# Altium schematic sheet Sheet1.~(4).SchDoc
size A3
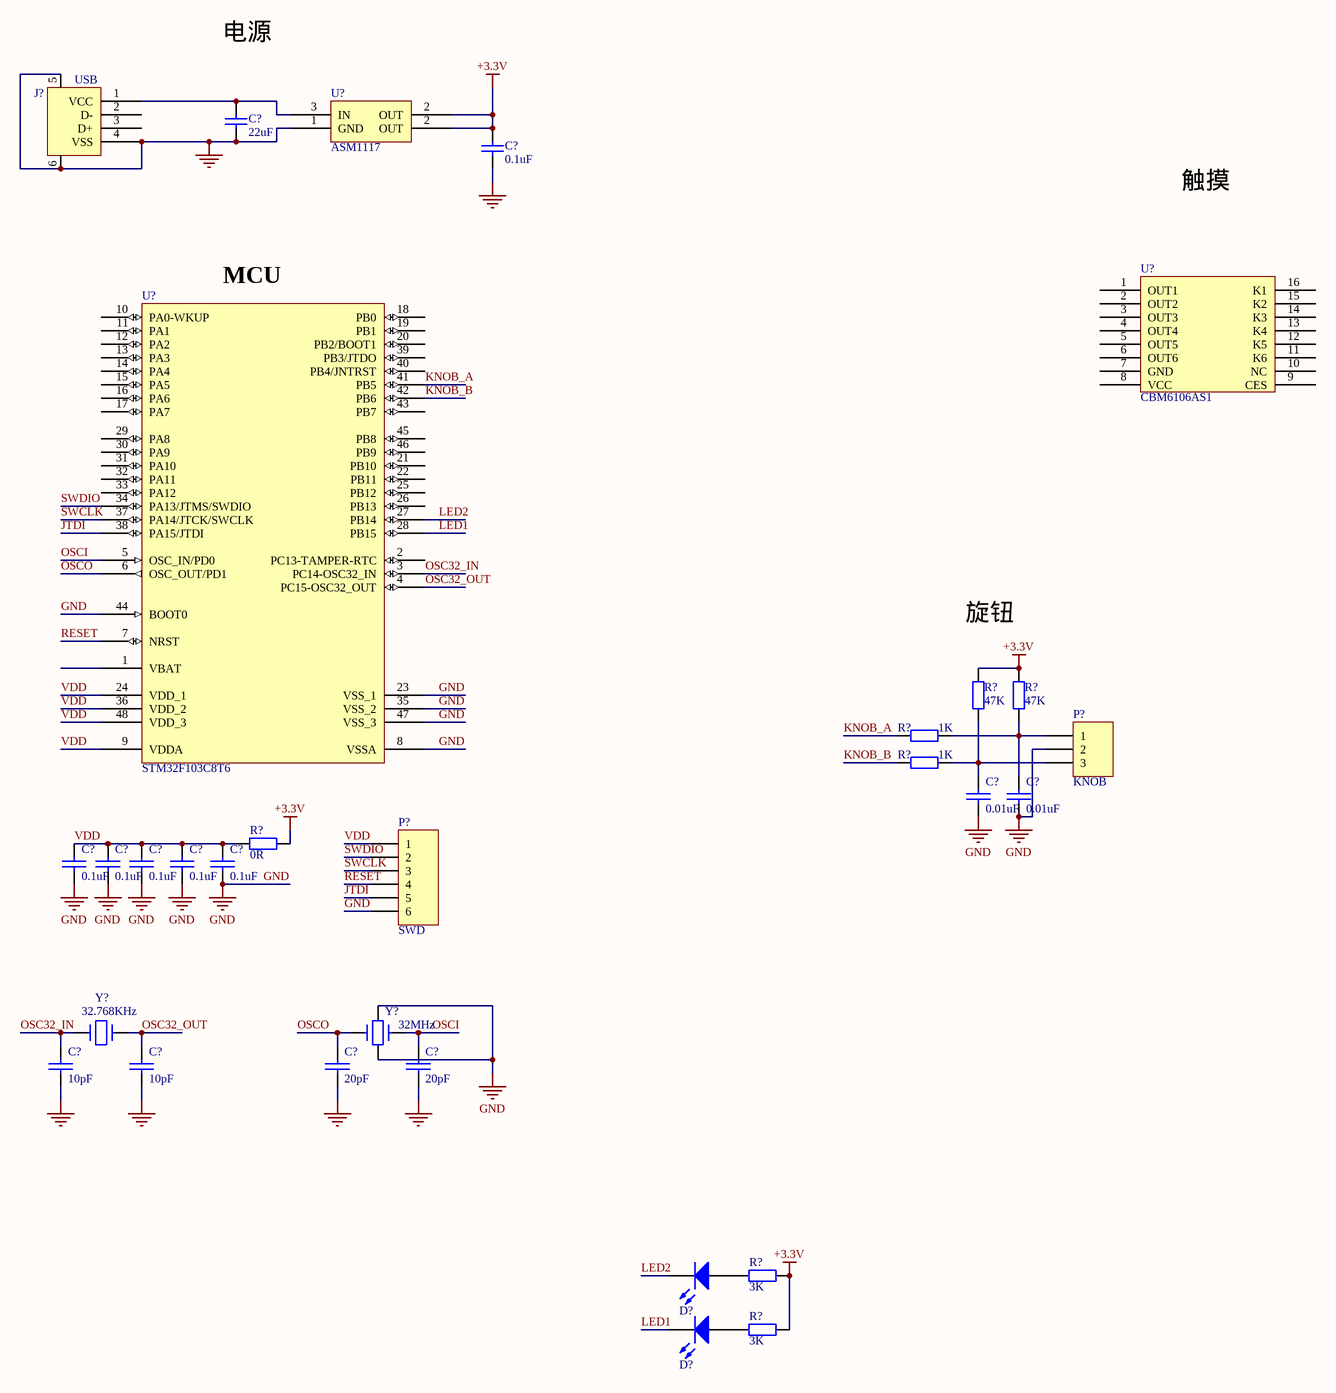
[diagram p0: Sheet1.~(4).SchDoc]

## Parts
(Parts that share a designator on the sheet are numbered #1, #2 ... from top to bottom, then left to right.)
C?#1  value 22uF  [0402C]  (hidden comment: Cap)
C?#2  value 0.1uF  [0402C]  (hidden comment: Cap)
C?#3  0.01uF  [0402C]
C?#4  0.01uF  [0402C]
C?#5  0.1uF  [0402C]
C?#6  0.1uF  [0402C]
C?#7  0.1uF  [0402C]
C?#8  0.1uF  [0402C]
C?#9  0.1uF  [0402C]
C?#10  10pF  [0402C]
C?#11  10pF  [0402C]
C?#12  20pF  [0402C]
C?#13  20pF  [0402C]
D?#1  LED0  [led0603]  (value not drawn)
D?#2  LED0  [led0603]  (value not drawn)
J?  USB  [USB_A1]
P?#1  KNOB  [HDR3X1_A]
P?#2  SWD  [HDR6X1_B2]
R?#1  value 47K  [0603-1]  (hidden comment: Res1)
R?#2  value 47K  [0603-1]  (hidden comment: Res1)
R?#3  value 1K  [0603-1]  (hidden comment: Res1)
R?#4  value 1K  [0603-1]  (hidden comment: Res1)
R?#5  value 0R  [0402R]  (hidden comment: Res1)
R?#6  value 3K  [0402R]  (hidden comment: Res1)
R?#7  value 3K  [0402R]  (hidden comment: Res1)
U?#1  ASM1117  [SOT-223-3]
U?#2  STM32F103C8T6  [LQFP48_N]
U?#3  CBM6106AS1
Y?#1  32.768KHz  [SMD3215]
Y?#2  32MHz  [Y3225]

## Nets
+3.3V: C?#2.2 R?#1.2 R?#2.2 R?#5.2 R?#6.1 R?#7.1 U?#1.2(OUT)
GND: C?#1.1 C?#2.1 C?#3.2 C?#4.2 C?#5.2 C?#6.2 C?#7.2 C?#8.2 C?#9.2 C?#10.2 C?#11.2 C?#12.2 C?#13.2 J?.4(VSS) J?.5 J?.6 P?#1.2 P?#2.6 U?#1.1(GND) U?#2.8(VSSA) U?#2.23(VSS_1) U?#2.35(VSS_2) U?#2.44(BOOT0) U?#2.47(VSS_3) Y?#2.2 Y?#2.4
JTDI: P?#2.5 U?#2.38(PA15/JTDI)
KNOB_A: R?#3.1 U?#2.41(PB5)
KNOB_B: R?#4.1 U?#2.42(PB6)
LED1: D?#2.2(K) U?#2.28(PB15)
LED2: D?#1.2(K) U?#2.27(PB14)
OSC32_IN: C?#10.1 U?#2.3(PC14-OSC32_IN) Y?#1.1
OSC32_OUT: C?#11.1 U?#2.4(PC15-OSC32_OUT) Y?#1.2
OSCI: C?#13.1 U?#2.5(OSC_IN/PD0) Y?#2.3
OSCO: C?#12.1 U?#2.6(OSC_OUT/PD1) Y?#2.1
RESET: P?#2.4 U?#2.7(NRST)
SWCLK: P?#2.3 U?#2.37(PA14/JTCK/SWCLK)
SWDIO: P?#2.2 U?#2.34(PA13/JTMS/SWDIO)
VDD: C?#5.1 C?#6.1 C?#7.1 C?#8.1 C?#9.1 P?#2.1 R?#5.1 U?#2.9(VDDA) U?#2.24(VDD_1) U?#2.36(VDD_2) U?#2.48(VDD_3)
NetC?#1_2: C?#1.2 J?.1(VCC) U?#1.3(IN)
NetC?#3_1: C?#3.1 P?#1.3 R?#1.1 R?#4.2
NetC?#4_1: C?#4.1 P?#1.1 R?#2.1 R?#3.2
NetD?#1_1: D?#1.1(A) R?#6.2
NetD?#2_1: D?#2.1(A) R?#7.2

Not connected (* = marked no-connect by the designer): J? 2(D-) 3(D+); U?#2 1(VBAT) 2(PC13-TAMPER-RTC) 10(PA0-WKUP) 11(PA1) 12(PA2) 13(PA3) 14(PA4) 15(PA5) 16(PA6) 17(PA7) 18(PB0) 19(PB1) 20(PB2/BOOT1) 21(PB10) 22(PB11) 25(PB12) 26(PB13) 29(PA8) 30(PA9) 31(PA10) 32(PA11) 33(PA12) 39(PB3/JTDO) 40(PB4/JNTRST) 43(PB7) 45(PB8) 46(PB9); U?#3 1(OUT1) 2(OUT2) 3(OUT3) 4(OUT4) 5(OUT5) 6(OUT6) 7(GND) 8(VCC) 9(CES) 10(NC) 11(K6) 12(K5) 13(K4) 14(K3) 15(K2) 16(K1)

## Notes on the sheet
- 电源
- 触摸
- (near U?#2) MCU
- 旋钮

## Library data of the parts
C?#1 C?#2 = Cap: 无极性电容
C?#3-C?#13 = CAP: Capacitor
D?#1 D?#2 = LED0: 发光二极管
J? = USB: USB接口
P?#1 = Header 3: 接插件
P?#2 = Header 6: 接插件
R?#1-R?#7 = Res1: 贴片电阻
U?#1 = ASM1117: 3.3V稳压芯片
U?#2 = STM32F103C8T6: STM32 ARM-based 32-bit MCU with 64 Kbytes Flash, 48-pin LQFP, Industrial Temperature
Y?#1 = CRYSTAL
Y?#2 = CRYSTAL1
